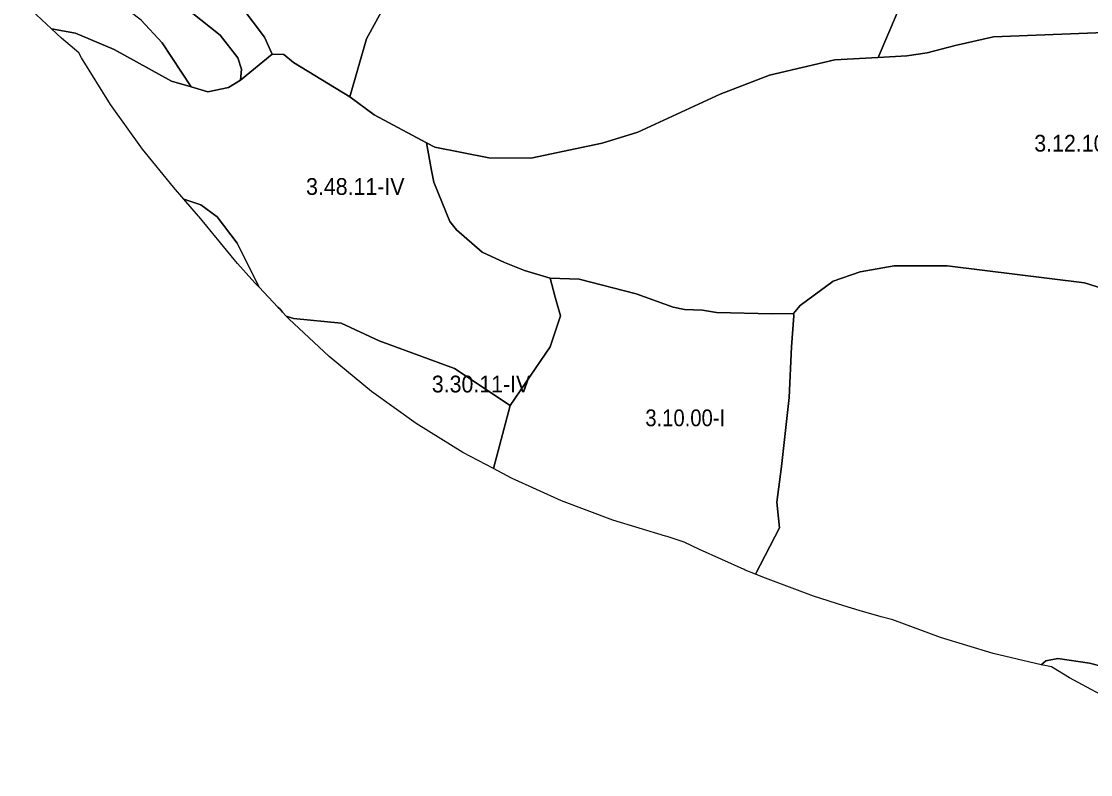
# Model space of a CAD drawing. Extents: x -591496 to -585489, y -1120610 to -1115685.
# Drawn here: x -590325 to -589052, y -1120546 to -1119649 of the extents above; entities that cross this region are included whole.
import ezdxf

# ---------------------------------------------------------------- set-up
doc = ezdxf.new("R2010")
doc.units = 0
doc.header["$LTSCALE"] = 8
doc.layers.add('40', color=7, linetype='Continuous', lineweight=25)
doc.layers.add('41', color=7, linetype='Continuous')

msp = doc.modelspace()

# ---------------------------------------------------------------- linework, layer by layer
at = {"layer": '40'}
for points in [[(-588953.5, -1119659), (-589167, -1119667.5), (-589213, -1119678), (-589246, -1119686.5), (-589270.5, -1119690), (-589304.495, -1119691.988), (-589282.5, -1119641), (-589274.5, -1119600.5), (-589276.5, -1119555), (-589276, -1119524), (-589268.5, -1119501.5), (-589255, -1119483.5), (-589183.5, -1119443), (-589153.5, -1119420.5), (-589137.5, -1119398), (-589126.5, -1119349.5), (-589107, -1119359), (-589132.5, -1119321.5), (-589104, -1119312), (-589088.5, -1119302.5), (-589079, -1119304), (-589012, -1119251)], [(-590089, -1119596), (-590035, -1119668), (-590026, -1119688), (-590063.5, -1119719), (-590062.5, -1119706), (-590067, -1119692.5), (-590088, -1119665.5), (-590178, -1119593.5)], [(-589889, -1119625), (-589913.5, -1119670), (-589933.5, -1119739), (-590000.5, -1119698), (-590012, -1119688.5), (-590026, -1119688), (-590035, -1119668), (-590089, -1119596)], [(-590182, -1119647.5), (-590157, -1119674.5), (-590122.567, -1119727.234), (-590146, -1119720.5), (-590214, -1119682.5), (-590260, -1119663), (-590288.534, -1119658.177), (-590324.527, -1119624.467)], [(-589282.5, -1119641), (-589304.495, -1119691.988), (-589356, -1119695), (-589434, -1119713), (-589492.5, -1119736), (-589590.5, -1119781), (-589633, -1119794), (-589718, -1119812), (-589768, -1119811.5), (-589832.5, -1119799), (-589842.356, -1119793.73), (-589904.5, -1119760.5), (-589933.5, -1119739), (-589913.5, -1119670), (-589889, -1119625)], [(-588977, -1119986.5), (-589059, -1119960.5), (-589222.5, -1119940.5), (-589285.5, -1119940.5), (-589326, -1119947.5), (-589358, -1119958.5), (-589397.5, -1119987.5), (-589405.143, -1119997.237), (-589430.5, -1119997.5), (-589497, -1119996), (-589513.5, -1119993), (-589535, -1119992.5), (-589548.5, -1119989.5), (-589592.5, -1119973.5), (-589660.5, -1119956), (-589695, -1119955), (-589725.5, -1119946), (-589749.5, -1119936.5), (-589776, -1119924), (-589806.5, -1119897.5), (-589814.5, -1119887.5), (-589833.5, -1119840.5), (-589836.075, -1119826.9), (-589842.356, -1119793.73), (-589832.5, -1119799), (-589768, -1119811.5), (-589718, -1119812), (-589633, -1119794), (-589590.5, -1119781), (-589492.5, -1119736), (-589434, -1119713), (-589356, -1119695), (-589304.495, -1119691.988), (-589270.5, -1119690), (-589246, -1119686.5), (-589213, -1119678), (-589167, -1119667.5), (-588953.5, -1119659)], [(-589300.809, -1120358.306), (-589327.117, -1120350.87), (-589345.337, -1120345.45), (-589381.649, -1120333.89), (-589441.668, -1120311.346), (-589450.493, -1120307.705), (-589422, -1120252.5), (-589425, -1120222), (-589419.5, -1120179.5), (-589410.5, -1120097), (-589407.5, -1120037), (-589404.814, -1120000), (-589405.143, -1119997.237), (-589397.5, -1119987.5), (-589358, -1119958.5), (-589326, -1119947.5), (-589285.5, -1119940.5), (-589222.5, -1119940.5), (-589059, -1119960.5), (-588977, -1119986.5)], [(-589008, -1120425), (-589053, -1120413.5), (-589090.5, -1120408), (-589105, -1120411), (-589110.384, -1120415.448), (-589167.689, -1120402.086), (-589230.31, -1120383.09), (-589287.077, -1120361.881), (-589300.809, -1120358.306)]]:
    msp.add_lwpolyline(points, dxfattribs=at)
for points in [[(-590063.5, -1119719), (-590078, -1119728), (-590102.5, -1119733), (-590122.567, -1119727.234), (-590157, -1119674.5), (-590182, -1119647.5), (-590264, -1119585), (-590272.5, -1119575.5), (-590276, -1119562), (-590270, -1119549.5), (-590261, -1119546.5), (-590242.5, -1119551.5), (-590178, -1119593.5), (-590088, -1119665.5), (-590067, -1119692.5), (-590062.5, -1119706)], [(-590122.567, -1119727.234), (-590102.5, -1119733), (-590078, -1119728), (-590063.5, -1119719), (-590026, -1119688), (-590012, -1119688.5), (-590000.5, -1119698), (-589933.5, -1119739), (-589904.5, -1119760.5), (-589842.356, -1119793.73), (-589836.075, -1119826.9), (-589833.5, -1119840.5), (-589814.5, -1119887.5), (-589806.5, -1119897.5), (-589776, -1119924), (-589749.5, -1119936.5), (-589725.5, -1119946), (-589695, -1119955), (-589689, -1119977.5), (-589682.704, -1120000), (-589695, -1120037), (-589742.5, -1120106.5), (-589809, -1120062.5), (-589898.5, -1120029.5), (-589944, -1120008.5), (-590000.5, -1120003), (-590009.102, -1120000.279), (-590013.52, -1119995.591), (-590016, -1119992.5), (-590019.069, -1119989.704), (-590041.545, -1119965.857), (-590067.5, -1119913.5), (-590091.5, -1119882), (-590111, -1119867.5), (-590130.988, -1119860.837), (-590143.463, -1119846.406), (-590180.283, -1119801.211), (-590218.4, -1119748.02), (-590252.955, -1119692.45), (-590256.241, -1119686.715), (-590276.766, -1119669.2), (-590288.534, -1119658.177), (-590260, -1119663), (-590214, -1119682.5), (-590146, -1119720.5)], [(-590067.5, -1119913.5), (-590041.545, -1119965.857), (-590046.506, -1119960.593), (-590067.076, -1119937.433), (-590071.24, -1119932.716), (-590112.753, -1119882.131), (-590113.588, -1119880.967), (-590130.988, -1119860.837), (-590111, -1119867.5), (-590091.5, -1119882)], [(-589405.143, -1119997.237), (-589404.814, -1120000), (-589407.5, -1120037), (-589410.5, -1120097), (-589419.5, -1120179.5), (-589425, -1120222), (-589422, -1120252.5), (-589450.493, -1120307.705), (-589462.678, -1120302.676), (-589463.903, -1120302.169), (-589517.2, -1120278.246), (-589535.268, -1120269.493), (-589555.688, -1120262.913), (-589557.649, -1120262.456), (-589620.269, -1120243.46), (-589681.513, -1120220.409), (-589741.119, -1120193.403), (-589762.654, -1120181.892), (-589742.5, -1120106.5), (-589695, -1120037), (-589682.704, -1120000), (-589689, -1119977.5), (-589695, -1119955), (-589660.5, -1119956), (-589592.5, -1119973.5), (-589548.5, -1119989.5), (-589535, -1119992.5), (-589513.5, -1119993), (-589497, -1119996), (-589430.5, -1119997.5)], [(-590016, -1119992.5), (-590013.52, -1119995.591), (-590019.069, -1119989.704)], [(-589742.5, -1120106.5), (-589762.654, -1120181.892), (-589798.83, -1120162.555), (-589854.4, -1120128), (-589907.591, -1120089.883), (-589958.176, -1120048.37), (-590005.937, -1120003.637), (-590009.102, -1120000.279), (-590000.5, -1120003), (-589944, -1120008.5), (-589898.5, -1120029.5), (-589809, -1120062.5)], [(-588803.039, -1120546.402), (-588811.135, -1120543.904), (-588837.759, -1120535.28), (-588874.545, -1120521.985), (-588935.115, -1120498.745), (-588959.573, -1120488.99), (-589019.179, -1120461.983), (-589076.89, -1120431.135), (-589098.173, -1120417.901), (-589103.96, -1120416.945), (-589110.384, -1120415.448), (-589105, -1120411), (-589090.5, -1120408), (-589053, -1120413.5), (-589008, -1120425), (-588973, -1120440)]]:
    msp.add_lwpolyline(points, close=True, dxfattribs=at)

# ---------------------------------------------------------------- texts
at = {"layer": '41'}
for s, width, p in [('3.12.10-II', 0.95, (-589118.625, -1119804.25)), ('3.48.11-IV', 0.95, (-589985.625, -1119855.813)), ('3.30.11-IV', 0.95, (-589835.875, -1120091.125)), ('3.10.00-I', 0.9, (-589581.688, -1120131.375))]:
    msp.add_text(s, height=20, dxfattribs=dict(at, width=width)).set_placement(p)

doc.saveas('drawing.dxf')
